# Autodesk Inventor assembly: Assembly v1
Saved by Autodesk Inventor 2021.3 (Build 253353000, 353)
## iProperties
Created: 2022-12
Part Number: Assembly v1
Document SubType Name: Assembly
Designer: AdminForWorker
Title: Assembly v1 v9
Author: AdminForWorker
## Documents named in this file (4)
- c:\worker\convert-fusion-r07-cosv3\tmp\job-1\184\output\files\052a9bb0-2290-4232-81d2-c0c3082fd4dc\daa4ff6a-6e35-4271-af89-fc4235b49390.iam
- c:\worker\convert-fusion-r07-cosv3\tmp\job-1\184\output\files\052a9bb0-2290-4232-81d2-c0c3082fd4dc\FX29 Load Cell v4.ipt
- c:\worker\convert-fusion-r07-cosv3\tmp\job-1\184\output\files\052a9bb0-2290-4232-81d2-c0c3082fd4dc\Enclosure Bottom v1 v7.ipt
- c:\worker\convert-fusion-r07-cosv3\tmp\job-1\184\output\files\052a9bb0-2290-4232-81d2-c0c3082fd4dc\Enclosure Top v1 v10.ipt
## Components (3 placed, 3 different names)
1. FX29 Load Cell v4:1
2. Enclosure Bottom v1 v7:1
3. Enclosure Top v1 v10:1
